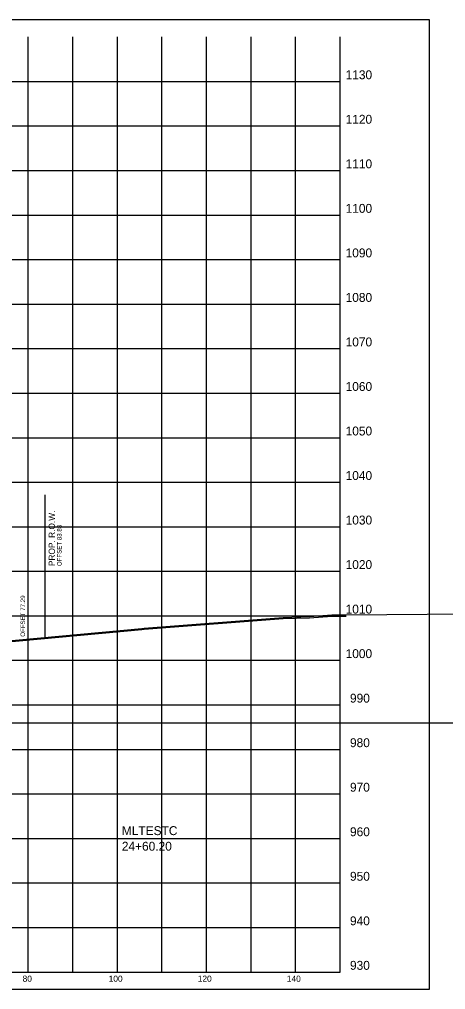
# Model space of a CAD drawing. Extents: x 1131015 to 1136271, y 133453 to 174329.
# Drawn here: x 1132418.5 to 1132514.1, y 156107.7 to 156325.6 of the extents above; entities that cross this region are included whole.
import ezdxf

# ---------------------------------------------------------------- set-up
doc = ezdxf.new("R2010")
doc.units = 0
for name, color, linetype in [('DESIGN - ROW - Right-of-Way and Easement Labels', 7, 'Continuous'), ('DESIGN - ROW - Right-of-Way Linework', 7, 'Continuous'), ('DESIGN - SHEET - Corner Text', 7, 'Continuous'), ('DESIGN - SHEET - Light Grid', 7, 'Continuous'), ('DESIGN - SHEET - Linework', 7, 'Continuous'), ('DESIGN - SHEET - Plot Shape', 7, 'Continuous'), ('DESIGN - TYPICAL - Slope Tie Text', 7, 'Continuous'), ('DESIGN - TYPICAL - Warning Text', 7, 'Continuous'), ('SURVEY - GROUND - Bottom of Topsoil Layer', 7, 'Continuous'), ('SURVEY - GROUND - Top of Ground', 7, 'Continuous')]:
    doc.layers.add(name, color=color, linetype=linetype)

msp = doc.modelspace()

# ---------------------------------------------------------------- linework, layer by layer
at = {"layer": 'DESIGN - ROW - Right-of-Way Linework'}
msp.add_line((1132424.28, 156186.81), (1132424.28, 156218.81), dxfattribs=at)
at = {"layer": 'DESIGN - SHEET - Light Grid'}
msp.add_line((1132340.46, 156167.66), (1132640.46, 156167.66), dxfattribs=at)
at = {"layer": 'DESIGN - SHEET - Linework'}
for p, q in [((1132420.46, 156111.66), (1132420.46, 156321.66)), ((1132430.46, 156111.66), (1132430.46, 156321.66)), ((1132440.46, 156111.66), (1132440.46, 156321.66)), ((1132450.46, 156111.66), (1132450.46, 156321.66)), ((1132460.46, 156111.66), (1132460.46, 156321.66)), ((1132470.46, 156111.66), (1132470.46, 156321.66)), ((1132480.46, 156111.66), (1132480.46, 156321.66)), ((1132190.46, 156311.66), (1132490.46, 156311.66)), ((1132190.46, 156301.66), (1132490.46, 156301.66)), ((1132190.46, 156291.66), (1132490.46, 156291.66)), ((1132190.46, 156281.66), (1132490.46, 156281.66)), ((1132190.46, 156271.66), (1132490.46, 156271.66)), ((1132190.46, 156261.66), (1132490.46, 156261.66)), ((1132190.46, 156251.66), (1132490.46, 156251.66)), ((1132190.46, 156241.66), (1132490.46, 156241.66)), ((1132190.46, 156231.66), (1132490.46, 156231.66)), ((1132190.46, 156221.66), (1132490.46, 156221.66)), ((1132190.46, 156211.66), (1132490.46, 156211.66)), ((1132190.46, 156201.66), (1132490.46, 156201.66)), ((1132190.46, 156191.66), (1132490.46, 156191.66)), ((1132190.46, 156181.66), (1132490.46, 156181.66)), ((1132190.46, 156171.66), (1132490.46, 156171.66)), ((1132190.46, 156161.66), (1132490.46, 156161.66)), ((1132190.46, 156151.66), (1132490.46, 156151.66)), ((1132190.46, 156141.66), (1132490.46, 156141.66)), ((1132190.46, 156131.66), (1132490.46, 156131.66)), ((1132190.46, 156121.66), (1132490.46, 156121.66))]:
    msp.add_line(p, q, dxfattribs=at)
msp.add_lwpolyline([(1132190.46, 156321.66), (1132190.46, 156111.66), (1132490.46, 156111.66), (1132490.46, 156321.66)], dxfattribs=at)
at = {"layer": 'DESIGN - SHEET - Plot Shape'}
msp.add_lwpolyline([(1132170.46, 156325.6), (1132510.46, 156325.6), (1132510.46, 156107.72), (1132170.46, 156107.72)], close=True, dxfattribs=at)
at = {"layer": 'SURVEY - GROUND - Bottom of Topsoil Layer'}
for p, q in [((1132446.48, 156188.64), (1132477.68, 156191.02)), ((1132477.68, 156191.02), (1132483.62, 156191.23)), ((1132483.62, 156191.23), (1132488.57, 156191.61)), ((1132488.57, 156191.61), (1132490.19, 156191.61)), ((1132490.19, 156191.61), (1132491.79, 156191.61)), ((1132409.46, 156185.18), (1132445.96, 156188.59)), ((1132445.96, 156188.59), (1132446.48, 156188.64))]:
    msp.add_line(p, q, dxfattribs=at)
at = {"layer": 'SURVEY - GROUND - Top of Ground'}
for p, q in [((1132483.62, 156191.48), (1132488.57, 156191.86)), ((1132488.57, 156191.86), (1132490.19, 156191.86)), ((1132490.19, 156191.86), (1132491.79, 156191.86)), ((1132491.79, 156191.86), (1132532.41, 156192.26)), ((1132446.48, 156188.89), (1132477.68, 156191.27)), ((1132477.68, 156191.27), (1132483.62, 156191.48)), ((1132409.46, 156185.43), (1132445.96, 156188.84)), ((1132445.96, 156188.84), (1132446.48, 156188.89))]:
    msp.add_line(p, q, dxfattribs=at)

# ---------------------------------------------------------------- texts
at = {"layer": 'DESIGN - ROW - Right-of-Way and Easement Labels'}
for s, height, p in [('PROP. R.O.W.', 1.4, (1132426.43, 156202.81)), ('OFFSET 83.83', 1, (1132427.93, 156202.81))]:
    msp.add_text(s, height=height, rotation=90, dxfattribs=at).set_placement(p)
at = {"layer": 'DESIGN - SHEET - Corner Text'}
for s, height, p in [('1130', 2, (1132491.7, 156312.16)), ('1120', 2, (1132491.7, 156302.16)), ('1110', 2, (1132491.7, 156292.16)), ('1100', 2, (1132491.7, 156282.16)), ('1090', 2, (1132491.7, 156272.16)), ('1080', 2, (1132491.7, 156262.16)), ('1070', 2, (1132491.7, 156252.16)), ('1060', 2, (1132491.7, 156242.16)), ('1050', 2, (1132491.7, 156232.16)), ('1040', 2, (1132491.7, 156222.16)), ('1030', 2, (1132491.7, 156212.16)), ('1020', 2, (1132491.7, 156202.16)), ('1010', 2, (1132491.7, 156192.16)), ('1000', 2, (1132491.7, 156182.16)), ('990', 2, (1132492.68, 156172.16)), ('980', 2, (1132492.68, 156162.16)), ('970', 2, (1132492.68, 156152.16)), ('960', 2, (1132492.68, 156142.16)), ('950', 2, (1132492.68, 156132.16)), ('940', 2, (1132492.68, 156122.16)), ('930', 2, (1132492.68, 156112.16)), ('80', 1.4, (1132419.19, 156109.46)), ('100', 1.4, (1132438.51, 156109.46)), ('120', 1.4, (1132458.51, 156109.46)), ('140', 1.4, (1132478.51, 156109.46))]:
    msp.add_text(s, height=height, dxfattribs=at).set_placement(p)
at = {"layer": 'DESIGN - TYPICAL - Slope Tie Text'}
msp.add_text('OFFSET 77.29', height=1, rotation=90, dxfattribs=at).set_placement((1132419.72, 156186.95))
at = {"layer": 'DESIGN - TYPICAL - Warning Text'}
for s, p in [('MLTESTC', (1132441.46, 156142.41)), ('24+60.20', (1132441.46, 156138.91))]:
    msp.add_text(s, height=2, dxfattribs=at).set_placement(p)

doc.saveas('drawing.dxf')
